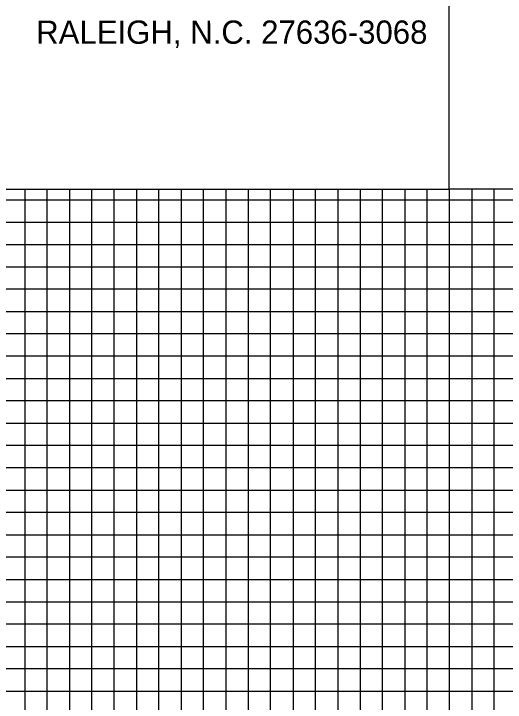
# Model space of a CAD drawing. Extents: x 2431000 to 2534000, y 645879 to 714000.
# Drawn here: x 2468176.3 to 2468286.3, y 669664.6 to 669818.8 of the extents above; entities that cross this region are included whole.
import ezdxf

# ---------------------------------------------------------------- set-up
doc = ezdxf.new("R2010")
doc.units = 0
for name, color, linetype in [('Sheet Clip Boundary CELL', 7, 'Continuous'), ('Sheet Cross Section CELL', 7, 'Continuous'), ('Sheet Cross Section Grid Major CELL', 7, 'Continuous'), ('Sheet North Arrow Point CELL', 7, 'Continuous'), ('Sheet Plan And Profile CELL', 7, 'Continuous')]:
    doc.layers.add(name, color=color, linetype=linetype)

msp = doc.modelspace()

# ---------------------------------------------------------------- linework, layer by layer
at = {"layer": 'Sheet Clip Boundary CELL'}
msp.add_lwpolyline([(2468173.7, 669779.51), (2468273.7, 669779.51), (2468273.7, 669917.06), (2468173.7, 669917.06)], close=True, dxfattribs=at)
at = {"layer": 'Sheet Cross Section CELL'}
for p, q in [((2468423.75, 669777.06), (2467023.75, 669777.06)), ((2468423.75, 669772.06), (2467023.75, 669772.06)), ((2467023.75, 669762.06), (2468423.75, 669762.06)), ((2468423.75, 669757.06), (2467023.75, 669757.06)), ((2467023.75, 669752.06), (2468423.75, 669752.06)), ((2468423.75, 669732.06), (2467023.75, 669732.06)), ((2467023.75, 669727.06), (2468423.75, 669727.06)), ((2468423.75, 669707.06), (2467023.75, 669707.06)), ((2467023.75, 669702.06), (2468423.75, 669702.06)), ((2468423.75, 669682.06), (2467023.75, 669682.06)), ((2467023.75, 669677.06), (2468423.75, 669677.06)), ((2468423.75, 669672.06), (2467023.75, 669672.06))]:
    msp.add_line(p, q, dxfattribs=at)
for points in [[(2468273.7, 669812.06), (2468273.75, 669812.06)], [(2468273.75, 669806.96), (2468273.7, 669806.96)], [(2468273.7, 669802.06), (2468273.75, 669802.06)], [(2468273.75, 669797.06), (2468273.7, 669797.06)], [(2468273.7, 669787.06), (2468273.75, 669787.06)], [(2468178.75, 669779.51), (2468178.75, 669417.06), (2468183.75, 669417.06), (2468183.75, 669779.51)], [(2468188.75, 669779.51), (2468188.75, 669417.06), (2468193.75, 669417.06), (2468193.75, 669779.51)], [(2468203.75, 669779.51), (2468203.75, 669417.06), (2468208.75, 669417.06), (2468208.75, 669779.51)], [(2468213.75, 669779.51), (2468213.75, 669417.06), (2468218.75, 669417.06), (2468218.75, 669779.51)], [(2468228.75, 669779.51), (2468228.75, 669417.06), (2468233.75, 669417.06), (2468233.75, 669779.51)], [(2468238.75, 669779.51), (2468238.75, 669417.06), (2468243.75, 669417.06), (2468243.75, 669779.51)], [(2468253.75, 669779.51), (2468253.75, 669417.06), (2468258.75, 669417.06), (2468258.75, 669779.51)], [(2468263.75, 669779.51), (2468263.75, 669417.06), (2468268.75, 669417.06), (2468268.75, 669779.51)], [(2468278.75, 669779.51), (2468278.75, 669417.06), (2468283.75, 669417.06), (2468283.75, 669779.51)], [(2468423.75, 669747.06), (2467023.75, 669747.06), (2467023.75, 669737.06), (2468423.75, 669737.06)], [(2468423.75, 669722.06), (2467023.75, 669722.06), (2467023.75, 669712.06), (2468423.75, 669712.06)], [(2468423.75, 669697.06), (2467023.75, 669697.06), (2467023.75, 669687.06), (2468423.75, 669687.06)]]:
    msp.add_lwpolyline(points, dxfattribs=at)
at = {"layer": 'Sheet Cross Section Grid Major CELL'}
for points in [[(2467698.75, 669917.06), (2467748.75, 669917.06), (2467748.75, 669417.06), (2467798.75, 669417.06), (2467798.75, 669917.06), (2467848.75, 669917.06), (2467848.75, 669417.06), (2467898.75, 669417.06), (2467898.75, 669917.06), (2467948.75, 669917.06), (2467948.75, 669417.06), (2467998.75, 669417.06), (2467998.75, 669917.06), (2468048.75, 669917.06), (2468048.75, 669417.06), (2468098.75, 669417.06), (2468098.75, 669917.06), (2468148.75, 669917.06), (2468148.75, 669417.06), (2468198.75, 669417.06), (2468198.75, 669779.51)], [(2468248.75, 669779.51), (2468248.75, 669417.06), (2468298.75, 669417.06), (2468298.75, 669779.51)], [(2468473.75, 669742.06), (2466973.75, 669742.06), (2466973.75, 669692.06), (2468298.75, 669692.06)]]:
    msp.add_lwpolyline(points, dxfattribs=at)
at = {"layer": 'Sheet North Arrow Point CELL'}
for points in [[(2468173.75, 669817.06), (2466973.75, 669817.06), (2466973.75, 669767.06), (2468473.75, 669767.06)], [(2468273.75, 669817.06), (2468273.7, 669817.06)], [(2468223.75, 669779.51), (2468223.75, 669417.06), (2468273.75, 669417.06), (2468273.75, 669779.51)], [(2468473.75, 669717.06), (2466973.75, 669717.06), (2466973.75, 669667.06), (2468473.75, 669667.06)]]:
    msp.add_lwpolyline(points, dxfattribs=at)
at = {"layer": 'Sheet Plan And Profile CELL'}
msp.add_lwpolyline([(2468273.7, 669892.01), (2468373.75, 669892.01), (2468373.75, 669779.51), (2468273.7, 669779.51)], close=True, dxfattribs=at)

# ---------------------------------------------------------------- texts
at = {"layer": 'Sheet Clip Boundary CELL'}
msp.add_text('RALEIGH, N.C. 27636-3068', height=5.2139, rotation=0.0107, dxfattribs=at).set_placement((2468181.26, 669812.05))

doc.saveas('drawing.dxf')
